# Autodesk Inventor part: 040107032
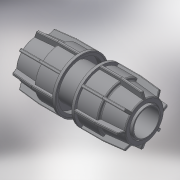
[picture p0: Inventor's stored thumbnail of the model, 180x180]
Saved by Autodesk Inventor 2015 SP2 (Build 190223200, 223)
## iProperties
Created: 2017-08
Part Number: 040107032
Material: Generic
Description: PLASSON IRRIFIT COUPLER 32-32
Document SubType Name: Modeling
Designer: KIM
Density: 1 g/cm^3
Appearance: Default
Author: KIM
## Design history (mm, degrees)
derived "040107.ipt"
feature "Solid1::040107.ipt"
tag "TaggingFeature1"
body "Solid1"
other parameters: "d5" = 48, "d6" = 24.2, "d10" = 57, "d22" = 44.8, "d24" = 2.53, "d25" = 51.3, "d26" = 45.6, "d31" = 1.28, "d49" = 2.85, "d50" = 0, "d58" = 0.64, "d61" = 360 deg, "d77" = 32, "d78" = 5 deg, "d80" = 35.2, "d81" = 55, "d82" = 3.3, "d84" = 5 deg, "d85" = 70 deg, "d86" = 54.15, "d87" = 0.55, "d88" = 0, "d89" = 48.45, "d90" = 5.5, "d91" = 0, "d93" = 180 deg, "d_" = 32, "E_" = 57, "l_nut" = 48
